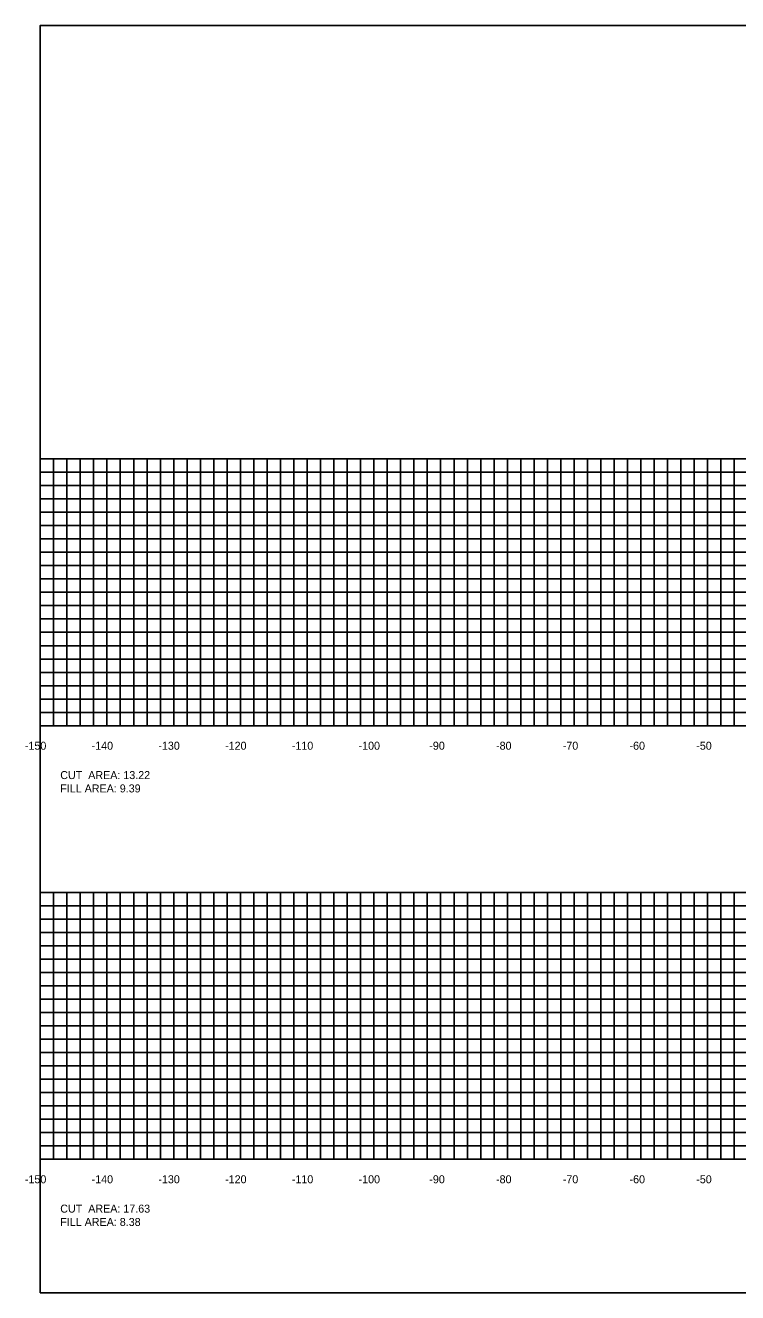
# Model space of a CAD drawing. Extents: x 1797645 to 1803805, y 248417 to 250269.
# Drawn here: x 1802478.8 to 1802585.5, y 250079.4 to 250269.4 of the extents above; entities that cross this region are included whole.
import ezdxf

# ---------------------------------------------------------------- set-up
doc = ezdxf.new("R2010")
doc.units = 0
for name, color, linetype in [('10', 7, 'Continuous'), ('60', 7, 'Continuous'), ('ANNO-TXT', 7, 'Continuous'), ('Level 62', 7, 'Continuous')]:
    doc.layers.add(name, color=color, linetype=linetype)

msp = doc.modelspace()

# ---------------------------------------------------------------- linework, layer by layer
msp.add_lwpolyline([(1802481, 250079.43), (1802781, 250079.43), (1802781, 250269.43), (1802481, 250269.43)], close=True)
at = {"layer": '60'}
for p, q in [((1802480.94, 250204.43), (1802481, 250204.43)), ((1802481, 250164.43), (1802481, 250204.43)), ((1802480.94, 250194.43), (1802481, 250194.43)), ((1802480.94, 250184.43), (1802481, 250184.43)), ((1802480.94, 250174.43), (1802481, 250174.43)), ((1802480.94, 250164.43), (1802481, 250164.43)), ((1802481, 250164.43), (1802781, 250164.43)), ((1802481, 250164.37), (1802481, 250164.43)), ((1802491, 250164.37), (1802491, 250164.43)), ((1802501, 250164.37), (1802501, 250164.43)), ((1802511, 250164.37), (1802511, 250164.43)), ((1802521, 250164.37), (1802521, 250164.43)), ((1802531, 250164.37), (1802531, 250164.43)), ((1802541, 250164.37), (1802541, 250164.43)), ((1802551, 250164.37), (1802551, 250164.43)), ((1802561, 250164.37), (1802561, 250164.43)), ((1802571, 250164.37), (1802571, 250164.43)), ((1802581, 250164.37), (1802581, 250164.43)), ((1802480.94, 250139.43), (1802481, 250139.43)), ((1802481, 250099.43), (1802481, 250139.43)), ((1802480.94, 250129.43), (1802481, 250129.43)), ((1802480.94, 250119.43), (1802481, 250119.43)), ((1802480.94, 250109.43), (1802481, 250109.43)), ((1802480.94, 250099.43), (1802481, 250099.43)), ((1802481, 250099.43), (1802781, 250099.43)), ((1802481, 250099.37), (1802481, 250099.43)), ((1802491, 250099.37), (1802491, 250099.43)), ((1802501, 250099.37), (1802501, 250099.43)), ((1802511, 250099.37), (1802511, 250099.43)), ((1802521, 250099.37), (1802521, 250099.43)), ((1802531, 250099.37), (1802531, 250099.43)), ((1802541, 250099.37), (1802541, 250099.43)), ((1802551, 250099.37), (1802551, 250099.43)), ((1802561, 250099.37), (1802561, 250099.43)), ((1802571, 250099.37), (1802571, 250099.43)), ((1802581, 250099.37), (1802581, 250099.43))]:
    msp.add_line(p, q, dxfattribs=at)
at = {"layer": 'Level 62'}
for p, q in [((1802481, 250204.43), (1802781, 250204.43)), ((1802481, 250164.43), (1802481, 250204.43)), ((1802483, 250164.43), (1802483, 250204.43)), ((1802485, 250164.43), (1802485, 250204.43)), ((1802487, 250164.43), (1802487, 250204.43)), ((1802489, 250164.43), (1802489, 250204.43)), ((1802491, 250164.43), (1802491, 250204.43)), ((1802493, 250164.43), (1802493, 250204.43)), ((1802495, 250164.43), (1802495, 250204.43)), ((1802497, 250164.43), (1802497, 250204.43)), ((1802499, 250164.43), (1802499, 250204.43)), ((1802501, 250164.43), (1802501, 250204.43)), ((1802503, 250164.43), (1802503, 250204.43)), ((1802505, 250164.43), (1802505, 250204.43)), ((1802507, 250164.43), (1802507, 250204.43)), ((1802509, 250164.43), (1802509, 250204.43)), ((1802511, 250164.43), (1802511, 250204.43)), ((1802513, 250164.43), (1802513, 250204.43)), ((1802515, 250164.43), (1802515, 250204.43)), ((1802517, 250164.43), (1802517, 250204.43)), ((1802519, 250164.43), (1802519, 250204.43)), ((1802521, 250164.43), (1802521, 250204.43)), ((1802523, 250164.43), (1802523, 250204.43)), ((1802525, 250164.43), (1802525, 250204.43)), ((1802527, 250164.43), (1802527, 250204.43)), ((1802529, 250164.43), (1802529, 250204.43)), ((1802531, 250164.43), (1802531, 250204.43)), ((1802533, 250164.43), (1802533, 250204.43)), ((1802535, 250164.43), (1802535, 250204.43)), ((1802537, 250164.43), (1802537, 250204.43)), ((1802539, 250164.43), (1802539, 250204.43)), ((1802541, 250164.43), (1802541, 250204.43)), ((1802543, 250164.43), (1802543, 250204.43)), ((1802545, 250164.43), (1802545, 250204.43)), ((1802547, 250164.43), (1802547, 250204.43)), ((1802549, 250164.43), (1802549, 250204.43)), ((1802551, 250164.43), (1802551, 250204.43)), ((1802553, 250164.43), (1802553, 250204.43)), ((1802555, 250164.43), (1802555, 250204.43)), ((1802557, 250164.43), (1802557, 250204.43)), ((1802559, 250164.43), (1802559, 250204.43)), ((1802561, 250164.43), (1802561, 250204.43)), ((1802563, 250164.43), (1802563, 250204.43)), ((1802565, 250164.43), (1802565, 250204.43)), ((1802567, 250164.43), (1802567, 250204.43)), ((1802569, 250164.43), (1802569, 250204.43)), ((1802571, 250164.43), (1802571, 250204.43)), ((1802573, 250164.43), (1802573, 250204.43)), ((1802575, 250164.43), (1802575, 250204.43)), ((1802577, 250164.43), (1802577, 250204.43)), ((1802579, 250164.43), (1802579, 250204.43)), ((1802581, 250164.43), (1802581, 250204.43)), ((1802583, 250164.43), (1802583, 250204.43)), ((1802585, 250164.43), (1802585, 250204.43)), ((1802481, 250202.43), (1802781, 250202.43)), ((1802481, 250200.43), (1802781, 250200.43)), ((1802481, 250198.43), (1802781, 250198.43)), ((1802481, 250196.43), (1802781, 250196.43)), ((1802481, 250194.43), (1802781, 250194.43)), ((1802481, 250192.43), (1802781, 250192.43)), ((1802481, 250190.43), (1802781, 250190.43)), ((1802481, 250188.43), (1802781, 250188.43)), ((1802481, 250186.43), (1802781, 250186.43)), ((1802481, 250184.43), (1802781, 250184.43)), ((1802481, 250182.43), (1802781, 250182.43)), ((1802481, 250180.43), (1802781, 250180.43)), ((1802481, 250178.43), (1802781, 250178.43)), ((1802481, 250176.43), (1802781, 250176.43)), ((1802481, 250174.43), (1802781, 250174.43)), ((1802481, 250172.43), (1802781, 250172.43)), ((1802481, 250170.43), (1802781, 250170.43)), ((1802481, 250168.43), (1802781, 250168.43)), ((1802481, 250166.43), (1802781, 250166.43)), ((1802481, 250164.43), (1802781, 250164.43)), ((1802481, 250139.43), (1802781, 250139.43)), ((1802481, 250099.43), (1802481, 250139.43)), ((1802483, 250099.43), (1802483, 250139.43)), ((1802485, 250099.43), (1802485, 250139.43)), ((1802487, 250099.43), (1802487, 250139.43)), ((1802489, 250099.43), (1802489, 250139.43)), ((1802491, 250099.43), (1802491, 250139.43)), ((1802493, 250099.43), (1802493, 250139.43)), ((1802495, 250099.43), (1802495, 250139.43)), ((1802497, 250099.43), (1802497, 250139.43)), ((1802499, 250099.43), (1802499, 250139.43)), ((1802501, 250099.43), (1802501, 250139.43)), ((1802503, 250099.43), (1802503, 250139.43)), ((1802505, 250099.43), (1802505, 250139.43)), ((1802507, 250099.43), (1802507, 250139.43)), ((1802509, 250099.43), (1802509, 250139.43)), ((1802511, 250099.43), (1802511, 250139.43)), ((1802513, 250099.43), (1802513, 250139.43)), ((1802515, 250099.43), (1802515, 250139.43)), ((1802517, 250099.43), (1802517, 250139.43)), ((1802519, 250099.43), (1802519, 250139.43)), ((1802521, 250099.43), (1802521, 250139.43)), ((1802523, 250099.43), (1802523, 250139.43)), ((1802525, 250099.43), (1802525, 250139.43)), ((1802527, 250099.43), (1802527, 250139.43)), ((1802529, 250099.43), (1802529, 250139.43)), ((1802531, 250099.43), (1802531, 250139.43)), ((1802533, 250099.43), (1802533, 250139.43)), ((1802535, 250099.43), (1802535, 250139.43)), ((1802537, 250099.43), (1802537, 250139.43)), ((1802539, 250099.43), (1802539, 250139.43)), ((1802541, 250099.43), (1802541, 250139.43)), ((1802543, 250099.43), (1802543, 250139.43)), ((1802545, 250099.43), (1802545, 250139.43)), ((1802547, 250099.43), (1802547, 250139.43)), ((1802549, 250099.43), (1802549, 250139.43)), ((1802551, 250099.43), (1802551, 250139.43)), ((1802553, 250099.43), (1802553, 250139.43)), ((1802555, 250099.43), (1802555, 250139.43)), ((1802557, 250099.43), (1802557, 250139.43)), ((1802559, 250099.43), (1802559, 250139.43)), ((1802561, 250099.43), (1802561, 250139.43)), ((1802563, 250099.43), (1802563, 250139.43)), ((1802565, 250099.43), (1802565, 250139.43)), ((1802567, 250099.43), (1802567, 250139.43)), ((1802569, 250099.43), (1802569, 250139.43)), ((1802571, 250099.43), (1802571, 250139.43)), ((1802573, 250099.43), (1802573, 250139.43)), ((1802575, 250099.43), (1802575, 250139.43)), ((1802577, 250099.43), (1802577, 250139.43)), ((1802579, 250099.43), (1802579, 250139.43)), ((1802581, 250099.43), (1802581, 250139.43)), ((1802583, 250099.43), (1802583, 250139.43)), ((1802585, 250099.43), (1802585, 250139.43)), ((1802481, 250137.43), (1802781, 250137.43)), ((1802481, 250135.43), (1802781, 250135.43)), ((1802481, 250133.43), (1802781, 250133.43)), ((1802481, 250131.43), (1802781, 250131.43)), ((1802481, 250129.43), (1802781, 250129.43)), ((1802481, 250127.43), (1802781, 250127.43)), ((1802481, 250125.43), (1802781, 250125.43)), ((1802481, 250123.43), (1802781, 250123.43)), ((1802481, 250121.43), (1802781, 250121.43)), ((1802481, 250119.43), (1802781, 250119.43)), ((1802481, 250117.43), (1802781, 250117.43)), ((1802481, 250115.43), (1802781, 250115.43)), ((1802481, 250113.43), (1802781, 250113.43)), ((1802481, 250111.43), (1802781, 250111.43)), ((1802481, 250109.43), (1802781, 250109.43)), ((1802481, 250107.43), (1802781, 250107.43)), ((1802481, 250105.43), (1802781, 250105.43)), ((1802481, 250103.43), (1802781, 250103.43)), ((1802481, 250101.43), (1802781, 250101.43)), ((1802481, 250099.43), (1802781, 250099.43))]:
    msp.add_line(p, q, dxfattribs=at)

# ---------------------------------------------------------------- texts
at = {"layer": '10'}
for s, p in [('-150', (1802478.7, 250160.83)), ('-140', (1802488.7, 250160.83)), ('-130', (1802498.7, 250160.83)), ('-120', (1802508.7, 250160.83)), ('-110', (1802518.7, 250160.83)), ('-100', (1802528.7, 250160.83)), ('-90', (1802539.3, 250160.83)), ('-80', (1802549.3, 250160.83)), ('-70', (1802559.3, 250160.83)), ('-60', (1802569.3, 250160.83)), ('-50', (1802579.3, 250160.83)), ('-150', (1802478.7, 250095.83)), ('-140', (1802488.7, 250095.83)), ('-130', (1802498.7, 250095.83)), ('-120', (1802508.7, 250095.83)), ('-110', (1802518.7, 250095.83)), ('-100', (1802528.7, 250095.83)), ('-90', (1802539.3, 250095.83)), ('-80', (1802549.3, 250095.83)), ('-70', (1802559.3, 250095.83)), ('-60', (1802569.3, 250095.83)), ('-50', (1802579.3, 250095.83))]:
    msp.add_text(s, height=1.2, dxfattribs=at).set_placement(p)
at = {"layer": '60'}
for p in [(1802481, 250164.43), (1802481, 250099.43)]:
    msp.add_text('-', height=0.0001, dxfattribs=at).set_placement(p)
at = {"layer": 'ANNO-TXT'}
for s, p in [('CUT  AREA: 13.22', (1802484, 250156.43)), ('FILL AREA: 9.39', (1802484, 250154.43)), ('CUT  AREA: 17.63', (1802484, 250091.43)), ('FILL AREA: 8.38', (1802484, 250089.43))]:
    msp.add_text(s, height=1.2, dxfattribs=at).set_placement(p)

doc.saveas('drawing.dxf')
